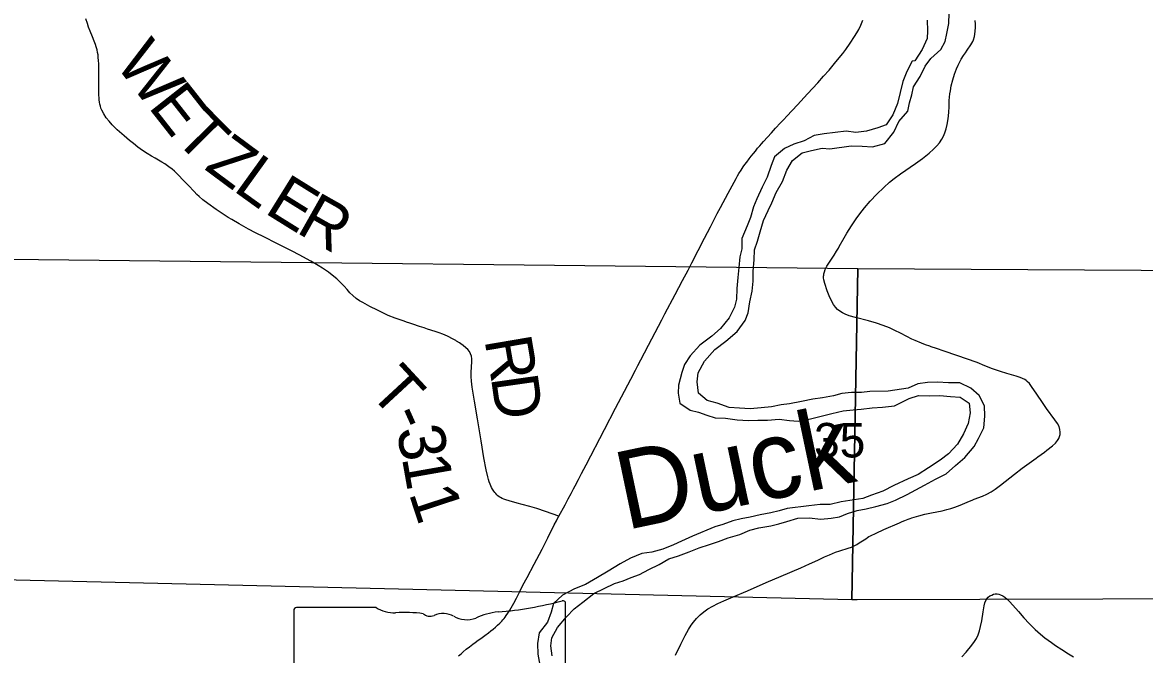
# Model space of a CAD drawing. Extents: x 0 to 34, y 0 to 22.
# Drawn here: x 4.406 to 5.767, y 15.933 to 16.7 of the extents above; entities that cross this region are included whole.
import ezdxf

# ---------------------------------------------------------------- set-up
doc = ezdxf.new("R2010")
doc.units = 0
for name, color, linetype in [('GM_X_Corporation', 7, 'Continuous'), ('GM_X_Major_River', 7, 'Continuous'), ('GM_X_Major_River_Text', 7, 'Continuous'), ('GM_X_Section_Text', 7, 'Continuous'), ('GM_X_State_Route', 7, 'Continuous'), ('GM_X_State_Shield', 7, 'Continuous'), ('GM_X_Township_Road', 7, 'Continuous'), ('GM_X_Township_Road_Text', 7, 'Continuous')]:
    doc.layers.add(name, color=color, linetype=linetype)

msp = doc.modelspace()

# ---------------------------------------------------------------- linework, layer by layer
at = {"layer": 'GM_X_Corporation'}
for points in [[(4.3887, 16.4128), (5.4192, 16.4015), (5.4121, 15.9993), (4.3982, 16.023), (4.3853, 16.0236)], [(5.4192, 16.4015), (6.4504, 16.3952), (6.4467, 16.0083), (5.8654, 16.0006), (5.4184, 15.9992), (5.4121, 15.9993)]]:
    msp.add_lwpolyline(points, close=True, dxfattribs=at)
at = {"layer": 'GM_X_Major_River'}
for points in [[(5.4689, 16.5796), (5.4799, 16.5923), (5.4821, 16.6022), (5.4846, 16.6121), (5.4868, 16.6216), (5.4947, 16.6342), (5.501, 16.6468), (5.5077, 16.6563), (5.5198, 16.6671), (5.525, 16.6766), (5.5272, 16.6865), (5.5297, 16.6987), (5.53, 16.7112)], [(5.5035, 16.7026), (5.5036, 16.6897), (5.5033, 16.6802), (5.4974, 16.6669), (5.4884, 16.6535)], [(5.4884, 16.6535), (5.485, 16.6527), (5.4787, 16.6405), (5.4738, 16.6283), (5.4674, 16.6016)], [(5.4674, 16.6016), (5.4616, 16.5879), (5.4538, 16.5756), (5.4436, 16.5721), (5.4296, 16.5681), (5.4167, 16.5664), (5.405, 16.5678), (5.3917, 16.5665), (5.3785, 16.5648), (5.3664, 16.5627), (5.354, 16.5561), (5.3415, 16.5521), (5.3302, 16.547), (5.3182, 16.537), (5.3142, 16.5263), (5.3091, 16.5122), (5.3032, 16.5), (5.2969, 16.4859), (5.2929, 16.476), (5.2892, 16.4634), (5.2852, 16.4531), (5.2786, 16.4379), (5.2784, 16.4253), (5.2763, 16.4155), (5.2749, 16.4025), (5.2739, 16.3904), (5.2726, 16.3771), (5.272, 16.3642), (5.2695, 16.3543), (5.2632, 16.3413), (5.2528, 16.3287), (5.2423, 16.3194), (5.2277, 16.3082), (5.2157, 16.2955), (5.209, 16.2848), (5.2057, 16.2753), (5.2018, 16.2597), (5.2012, 16.2502), (5.2032, 16.2381), (5.2158, 16.2296), (5.2261, 16.227), (5.236, 16.2234), (5.2463, 16.2201), (5.2588, 16.2199), (5.2729, 16.2178), (5.2865, 16.2169), (5.2979, 16.2174), (5.3096, 16.2175), (5.3237, 16.2185), (5.3362, 16.2168), (5.3468, 16.2162), (5.3619, 16.219), (5.3876, 16.2254), (5.4016, 16.2287), (5.4134, 16.23), (5.4232, 16.2308), (5.4368, 16.2322), (5.4493, 16.2331), (5.4637, 16.2348), (5.4816, 16.2438)], [(5.4803, 16.2563), (5.4559, 16.2525), (5.4339, 16.2522), (5.4237, 16.251), (5.4116, 16.2508), (5.3998, 16.2495), (5.3896, 16.2467), (5.3764, 16.2446), (5.3647, 16.2429), (5.351, 16.2401), (5.3363, 16.2373), (5.3261, 16.236), (5.3147, 16.2335), (5.3019, 16.2322), (5.2886, 16.2309), (5.2757, 16.2319), (5.2632, 16.2325), (5.2487, 16.238), (5.2365, 16.2412), (5.2262, 16.2502), (5.2245, 16.2638), (5.2258, 16.2748), (5.2332, 16.289), (5.2459, 16.3032), (5.2591, 16.3132), (5.2729, 16.3251), (5.2826, 16.3382), (5.2863, 16.3477), (5.2884, 16.361), (5.2912, 16.3739), (5.2922, 16.3861), (5.2924, 16.3982), (5.2937, 16.4119), (5.294, 16.424), (5.2976, 16.4347), (5.3009, 16.4458), (5.3048, 16.4595), (5.3104, 16.4717), (5.3148, 16.4812), (5.3203, 16.4934), (5.3277, 16.5068), (5.3332, 16.5205), (5.3402, 16.5324), (5.3519, 16.5416), (5.3632, 16.5444), (5.3761, 16.5473), (5.3855, 16.5466), (5.4113, 16.55), (5.4246, 16.5498), (5.4371, 16.5489), (5.4522, 16.5532), (5.463, 16.5667), (5.4689, 16.5796)], [(5.4793, 16.1272), (5.4898, 16.1326), (5.5, 16.1384), (5.5136, 16.1457), (5.5265, 16.1523), (5.5378, 16.1623), (5.549, 16.1719), (5.5603, 16.1853), (5.5655, 16.1952), (5.5719, 16.2082), (5.5732, 16.2222), (5.5727, 16.2348), (5.5666, 16.2472), (5.5562, 16.2563), (5.5429, 16.2626), (5.5292, 16.2628), (5.5159, 16.2635), (5.5038, 16.263), (5.4921, 16.2613), (5.4803, 16.2563)], [(5.4816, 16.2438), (5.4929, 16.2473), (5.5062, 16.247), (5.5187, 16.2472), (5.5317, 16.2461), (5.5434, 16.2451), (5.5545, 16.238), (5.5554, 16.2262), (5.5532, 16.2133), (5.5473, 16.2007), (5.5402, 16.1881), (5.5293, 16.1763), (5.5191, 16.1686), (5.5051, 16.1593), (5.4923, 16.1516), (5.4802, 16.1462)], [(5.4802, 16.1462), (5.4628, 16.1381), (5.4496, 16.1311), (5.436, 16.1263), (5.4254, 16.1224), (5.399, 16.1182), (5.3857, 16.115), (5.3736, 16.1152), (5.36, 16.1135), (5.3335, 16.1102), (5.3237, 16.1074), (5.3138, 16.105), (5.301, 16.1025), (5.2885, 16.0997), (5.2779, 16.0976), (5.2677, 16.0952), (5.2556, 16.0909), (5.2458, 16.0881), (5.2187, 16.0764), (5.2055, 16.0705), (5.1957, 16.0662), (5.1829, 16.0607), (5.1693, 16.0571), (5.1572, 16.0554), (5.1436, 16.0499), (5.1308, 16.0429), (5.1165, 16.034), (5.1033, 16.0266), (5.0891, 16.0181), (5.0755, 16.0126), (5.0612, 16.0052), (5.0503, 15.9948), (5.0474, 15.9845), (5.0427, 15.9723), (5.0326, 15.9593), (5.0309, 15.9464), (5.0311, 15.9335), (5.0335, 15.9202)], [(5.0485, 15.9314), (5.0468, 15.9435), (5.0482, 15.9534), (5.0549, 15.9657), (5.0661, 15.9787), (5.0754, 15.9883), (5.0859, 15.9964), (5.0991, 16.0072), (5.1115, 16.0131), (5.1243, 16.0193), (5.1345, 16.0225), (5.1443, 16.0264), (5.1545, 16.03), (5.1658, 16.0362), (5.1782, 16.0424), (5.1902, 16.049), (5.2016, 16.0526), (5.2148, 16.0577), (5.2268, 16.0624), (5.2393, 16.0664), (5.2502, 16.07), (5.2619, 16.0747), (5.2763, 16.0787), (5.2883, 16.0837), (5.2993, 16.0866), (5.3137, 16.089), (5.3235, 16.0914), (5.3333, 16.0942), (5.3465, 16.0986), (5.3602, 16.0988), (5.3742, 16.0974), (5.3871, 16.0984), (5.3969, 16.1), (5.4067, 16.1039), (5.4184, 16.1079), (5.4294, 16.1099), (5.4411, 16.1127), (5.4547, 16.1163), (5.4649, 16.1203), (5.4793, 16.1272)]]:
    msp.add_lwpolyline(points, dxfattribs=at)
at = {"layer": 'GM_X_State_Route'}
for points in [[(5.2527, 16.4752), (5.2619, 16.4926), (5.2716, 16.5106), (5.2734, 16.5138), (5.2751, 16.5166), (5.2776, 16.5206), (5.2802, 16.5245), (5.2822, 16.5274), (5.2845, 16.5305), (5.2874, 16.5344), (5.2898, 16.5375), (5.2926, 16.5409), (5.295, 16.5439), (5.2977, 16.5472), (5.3003, 16.5503), (5.3024, 16.5527), (5.3048, 16.5554), (5.3096, 16.5607), (5.3147, 16.5661), (5.3196, 16.5717), (5.3256, 16.578), (5.3294, 16.5822), (5.333, 16.5861), (5.3459, 16.5999), (5.3581, 16.6131), (5.3708, 16.6267), (5.3778, 16.6345), (5.3844, 16.642), (5.3926, 16.6519), (5.4009, 16.6621), (5.4046, 16.667), (5.41, 16.6746), (5.4154, 16.6828), (5.4181, 16.6872), (5.4204, 16.6915), (5.4228, 16.6966), (5.4254, 16.7027)], [(4.9902, 15.9768), (4.9915, 15.9784), (4.9927, 15.9802), (4.9948, 15.9832), (4.9972, 15.987), (5.002, 15.9953), (5.0052, 16.0015), (5.0089, 16.0088), (5.013, 16.017), (5.0181, 16.0266), (5.0267, 16.0428), (5.0362, 16.0608), (5.0432, 16.0747), (5.0511, 16.0902), (5.0536, 16.0951), (5.0547, 16.0973), (5.0566, 16.1007), (5.0642, 16.1148), (5.068, 16.1219), (5.0715, 16.1285), (5.0744, 16.1339), (5.0765, 16.1378), (5.0805, 16.1455), (5.0841, 16.1527), (5.0896, 16.1631), (5.1119, 16.2061), (5.1253, 16.232), (5.1325, 16.2457), (5.144, 16.267), (5.1497, 16.2781), (5.1525, 16.2836), (5.1562, 16.2907), (5.1605, 16.299), (5.1654, 16.3083), (5.1774, 16.3314), (5.1814, 16.3391), (5.1852, 16.3462), (5.1976, 16.3699), (5.2066, 16.3869), (5.2133, 16.3995), (5.2179, 16.4083), (5.2334, 16.4381), (5.2405, 16.4519), (5.2488, 16.4679), (5.2527, 16.4752)], [(4.9349, 15.9312), (4.938, 15.934), (4.9405, 15.9362), (4.9444, 15.9394), (4.9482, 15.9424), (4.9521, 15.9455), (4.9552, 15.9477), (4.9588, 15.9503), (4.9618, 15.9525), (4.9667, 15.9561), (4.9712, 15.9594), (4.9741, 15.9616), (4.977, 15.9639), (4.9798, 15.9663), (4.9823, 15.9684), (4.9851, 15.971), (4.9874, 15.9735), (4.9888, 15.975), (4.9902, 15.9768)]]:
    msp.add_lwpolyline(points, dxfattribs=at)
at = {"layer": 'GM_X_State_Shield'}
for p, q in [((5.0648, 15.8903), (5.0648, 15.9949)), ((4.7352, 15.9865), (4.7352, 15.7864)), ((4.8349, 15.99), (4.7384, 15.99))]:
    msp.add_line(p, q, dxfattribs=at)
for centre, major_axis, start_param, end_param in [((4.9474, 16.2628), (0.3495, 0), 4.814394, 5.042369), ((5.0611, 15.9954), (0.00367, 0), 6.141152, 7.989035), ((4.739, 15.987), (0.00382, 0), 1.712693, 3.28349), ((4.8579, 16.0132), (0.037, 0), 4.042523, 4.731795), ((4.8702, 15.8776), (0.133, 0), 1.404758, 1.657858), ((4.9004, 15.988), (0.0107, 0), 3.836095, 5.185415), ((4.9161, 15.9649), (0.0222, 0), 0.950623, 2.079405), ((4.9448, 15.9966), (0.0267, 0), 4.081561, 5.145723), ((4.9919, 15.9289), (0.0703, 0), 1.699011, 2.107814)]:
    msp.add_ellipse(centre, major_axis=major_axis, ratio=0.8, start_param=start_param, end_param=end_param, dxfattribs=at)
at = {"layer": 'GM_X_Township_Road'}
for points in [[(5.0566, 16.1007), (5.0487, 16.1037), (5.0403, 16.1065), (5.0299, 16.11), (5.0216, 16.1125), (5.012, 16.115), (5.006, 16.1166), (4.9965, 16.1194), (4.9924, 16.1207), (4.99, 16.1215), (4.9879, 16.1224), (4.986, 16.1234), (4.9843, 16.1245), (4.9828, 16.1257), (4.9815, 16.1269), (4.98, 16.1283), (4.9789, 16.1295), (4.9776, 16.1311), (4.9761, 16.1335), (4.975, 16.1356), (4.9732, 16.1396), (4.9721, 16.1425), (4.9712, 16.1454), (4.9704, 16.1484), (4.9686, 16.1569), (4.9658, 16.1715), (4.9622, 16.1922), (4.9602, 16.2045), (4.958, 16.2191), (4.9543, 16.2404), (4.9515, 16.2573), (4.9507, 16.2646), (4.9503, 16.2702), (4.9503, 16.2751), (4.9507, 16.2819), (4.9511, 16.2881), (4.951, 16.2918), (4.9505, 16.2949), (4.9495, 16.2978), (4.9481, 16.3006), (4.9462, 16.303), (4.944, 16.3052), (4.9406, 16.3078), (4.9377, 16.3099), (4.9362, 16.311), (4.9326, 16.3133), (4.9315, 16.3139), (4.9283, 16.3158), (4.9217, 16.3192), (4.916, 16.3217), (4.9114, 16.3234), (4.9067, 16.3249), (4.8972, 16.3279), (4.8931, 16.3292), (4.8878, 16.3309), (4.8795, 16.3337), (4.8748, 16.3353), (4.8731, 16.3359), (4.8678, 16.3377), (4.8579, 16.3412), (4.8498, 16.3445), (4.8441, 16.347), (4.8341, 16.3519), (4.8297, 16.3541), (4.8275, 16.3553), (4.8187, 16.36), (4.815, 16.3622), (4.8109, 16.365), (4.8066, 16.3685), (4.8031, 16.372), (4.7998, 16.3757), (4.7961, 16.3798), (4.7927, 16.3835), (4.7873, 16.3887), (4.7817, 16.3934), (4.7772, 16.3968), (4.7747, 16.3987), (4.7701, 16.4017), (4.7648, 16.4049), (4.7557, 16.4101), (4.7415, 16.4179), (4.7333, 16.4222), (4.7234, 16.4273), (4.7201, 16.429), (4.7162, 16.431), (4.7079, 16.4351), (4.7051, 16.4365), (4.6996, 16.4392), (4.6885, 16.4448), (4.6802, 16.4491), (4.6688, 16.4554), (4.6598, 16.4608), (4.6555, 16.4634), (4.6508, 16.4665), (4.641, 16.473), (4.6309, 16.4802), (4.625, 16.4847), (4.6203, 16.4888), (4.6176, 16.4913), (4.6141, 16.4948), (4.6074, 16.502), (4.6014, 16.5083), (4.595, 16.515), (4.5905, 16.5193), (4.5876, 16.5217), (4.5837, 16.5247), (4.5786, 16.5282), (4.5749, 16.5305), (4.5669, 16.5352), (4.5626, 16.5376), (4.5573, 16.5409), (4.5516, 16.5446), (4.5461, 16.5486), (4.5407, 16.5528), (4.5359, 16.5567), (4.5292, 16.5622), (4.5209, 16.5697), (4.5148, 16.5757), (4.5111, 16.5799), (4.5077, 16.5843), (4.5046, 16.589), (4.5024, 16.5934), (4.5012, 16.596), (4.5005, 16.5983), (4.4998, 16.6006), (4.4993, 16.6033), (4.499, 16.606), (4.4986, 16.6139), (4.4985, 16.6269), (4.4988, 16.6418), (4.4987, 16.6498), (4.4984, 16.6537), (4.498, 16.6573), (4.4977, 16.6605), (4.4972, 16.6635), (4.4965, 16.6668), (4.4956, 16.6701), (4.4947, 16.673), (4.4932, 16.6771), (4.4911, 16.6823), (4.4882, 16.6891), (4.4862, 16.6943), (4.4848, 16.6987), (4.4828, 16.7043)], [(5.1983, 15.9321), (5.2045, 15.9456), (5.2098, 15.9561), (5.2137, 15.9632), (5.2171, 15.9684), (5.22, 15.9724), (5.2237, 15.9766), (5.2281, 15.981), (5.2323, 15.9847), (5.2373, 15.9883), (5.2432, 15.9918), (5.2493, 15.995), (5.2566, 15.9983), (5.2681, 16.003), (5.2854, 16.0101), (5.308, 16.0203), (5.3264, 16.0279), (5.3503, 16.0383), (5.3605, 16.0429), (5.3706, 16.0476), (5.379, 16.0516), (5.3847, 16.0541), (5.3923, 16.057), (5.3976, 16.0588), (5.4076, 16.062), (5.4117, 16.0634), (5.414, 16.0644), (5.4179, 16.0663), (5.421, 16.0683), (5.4288, 16.0735), (5.4311, 16.0751), (5.4326, 16.076), (5.4346, 16.077), (5.4413, 16.0803), (5.4509, 16.0846), (5.4697, 16.0929), (5.4731, 16.0943), (5.4764, 16.0957), (5.4784, 16.0965), (5.4805, 16.0974), (5.4826, 16.0982), (5.4846, 16.0988), (5.4877, 16.0998), (5.4934, 16.1013), (5.5007, 16.1032), (5.5086, 16.1048), (5.5214, 16.1074), (5.5274, 16.1088), (5.5322, 16.1102), (5.5369, 16.1117), (5.5433, 16.1142), (5.5518, 16.1178), (5.5587, 16.1206), (5.5604, 16.1214), (5.5703, 16.1252), (5.5759, 16.1277), (5.5808, 16.1303), (5.586, 16.1337), (5.5924, 16.1385), (5.6094, 16.1518), (5.6187, 16.1589), (5.6272, 16.1652), (5.6327, 16.1692), (5.6356, 16.1714), (5.6376, 16.1728), (5.6456, 16.1786), (5.6486, 16.1809), (5.6554, 16.1862), (5.6591, 16.1896), (5.6614, 16.1925), (5.663, 16.1951), (5.6639, 16.1974), (5.6645, 16.1998), (5.6647, 16.2029), (5.6644, 16.206), (5.6633, 16.2096), (5.6613, 16.2134), (5.6581, 16.2179), (5.6482, 16.2315), (5.6432, 16.2386), (5.6363, 16.2489), (5.6301, 16.2582), (5.6274, 16.2617), (5.6248, 16.2644), (5.6234, 16.2656), (5.6219, 16.2666), (5.6191, 16.268), (5.6163, 16.2692), (5.6115, 16.2707), (5.6001, 16.2738), (5.5924, 16.2762), (5.5825, 16.2798), (5.5732, 16.2834), (5.564, 16.2871), (5.5394, 16.2959), (5.5241, 16.301), (5.5147, 16.3042), (5.5083, 16.3065), (5.5066, 16.3071), (5.5013, 16.3089), (5.4966, 16.3106), (5.4886, 16.3139), (5.4847, 16.3158), (5.4786, 16.3188), (5.4709, 16.3228), (5.4642, 16.3261), (5.4575, 16.3292), (5.45, 16.3322), (5.4419, 16.335), (5.4323, 16.3377), (5.4163, 16.342), (5.4086, 16.3441), (5.4039, 16.3458), (5.4006, 16.3475), (5.3974, 16.3494), (5.3945, 16.3517), (5.392, 16.3544), (5.3898, 16.3575), (5.3877, 16.3613), (5.3846, 16.368), (5.3821, 16.3744), (5.3792, 16.3832), (5.378, 16.3874), (5.3777, 16.3899), (5.3778, 16.3922), (5.3779, 16.3933), (5.3781, 16.3949), (5.3787, 16.3973), (5.3798, 16.4001), (5.3818, 16.404), (5.3859, 16.4102), (5.3906, 16.4174), (5.3935, 16.4222), (5.3957, 16.4259), (5.3968, 16.4281), (5.4027, 16.4384), (5.4061, 16.4443), (5.4086, 16.4486), (5.4116, 16.4533), (5.4171, 16.4615), (5.4215, 16.4676), (5.4272, 16.4749), (5.4342, 16.4829), (5.4423, 16.4914), (5.4506, 16.4998), (5.4575, 16.506), (5.4633, 16.5107), (5.4709, 16.5161), (5.4893, 16.5287), (5.4978, 16.535), (5.5056, 16.5412), (5.5112, 16.5461), (5.5151, 16.5501), (5.5182, 16.554), (5.521, 16.5581), (5.523, 16.5619), (5.5247, 16.5659), (5.5262, 16.5707), (5.5275, 16.5761), (5.5287, 16.5828), (5.5296, 16.5908), (5.53, 16.5977), (5.5302, 16.6051), (5.5306, 16.6094), (5.5309, 16.6131), (5.5315, 16.6168), (5.5326, 16.6229), (5.5345, 16.6301), (5.5367, 16.6372), (5.5391, 16.6437), (5.541, 16.6482), (5.5447, 16.6554), (5.5473, 16.6597), (5.5497, 16.6632), (5.5519, 16.6662), (5.5565, 16.6729), (5.5587, 16.6766), (5.5597, 16.6789), (5.5607, 16.6828), (5.5616, 16.689), (5.5621, 16.6942), (5.5621, 16.6979), (5.5616, 16.7022)], [(5.5453, 15.9301), (5.5507, 15.936), (5.5575, 15.9442), (5.5608, 15.9487), (5.563, 15.9524), (5.5651, 15.9569), (5.5668, 15.9616), (5.5682, 15.967), (5.5695, 15.9737), (5.5711, 15.9848), (5.5723, 15.9922), (5.5732, 15.9958), (5.5744, 15.9986), (5.5758, 16.0007), (5.5774, 16.0025), (5.5794, 16.004), (5.5816, 16.0052), (5.5839, 16.0061), (5.5857, 16.0065), (5.5882, 16.0065), (5.5901, 16.0062), (5.5924, 16.0054), (5.5952, 16.004), (5.5975, 16.0025), (5.6004, 16.0002), (5.6037, 15.9968), (5.6143, 15.9852), (5.6208, 15.9775), (5.627, 15.9705), (5.6343, 15.9633), (5.6407, 15.9575), (5.6461, 15.9534), (5.6543, 15.9475), (5.6591, 15.9441), (5.6668, 15.9391), (5.6749, 15.9339), (5.6807, 15.9303)]]:
    msp.add_lwpolyline(points, dxfattribs=at)

# ---------------------------------------------------------------- texts
at = {"layer": 'GM_X_Major_River_Text'}
msp.add_text('Duck', height=0.0947, rotation=11.9039, dxfattribs=at).set_placement((5.1374, 16.0837))
at = {"layer": 'GM_X_Section_Text'}
msp.add_text('35', height=0.04186, rotation=0, dxfattribs=at).set_placement((5.3661, 16.1721))
at = {"layer": 'GM_X_Township_Road_Text'}
for s, rotation, p in [('W', 307.5312, (4.5171, 16.6502)), ('E', 308.1791, (4.5577, 16.5975)), ('T', 314.735, (4.5885, 16.5588)), ('Z', 323.387, (4.6254, 16.5226)), ('L', 324.2306, (4.6602, 16.4967)), ('E', 328.1119, (4.6982, 16.4696)), ('R', 330.5625, (4.7365, 16.4458)), ('R', 279.6587, (4.9663, 16.315)), ('T', 312.7782, (4.8246, 16.2511)), ('D', 278.0992, (4.9741, 16.2694)), ('-', 294.0719, (4.8508, 16.224)), ('3', 281.2446, (4.8593, 16.2059)), ('1', 280.0167, (4.8661, 16.1719)), ('1', 288.2116, (4.8743, 16.1288))]:
    msp.add_text(s, height=0.0568, rotation=rotation, dxfattribs=at).set_placement(p)

doc.saveas('drawing.dxf')
